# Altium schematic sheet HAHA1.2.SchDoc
size A1
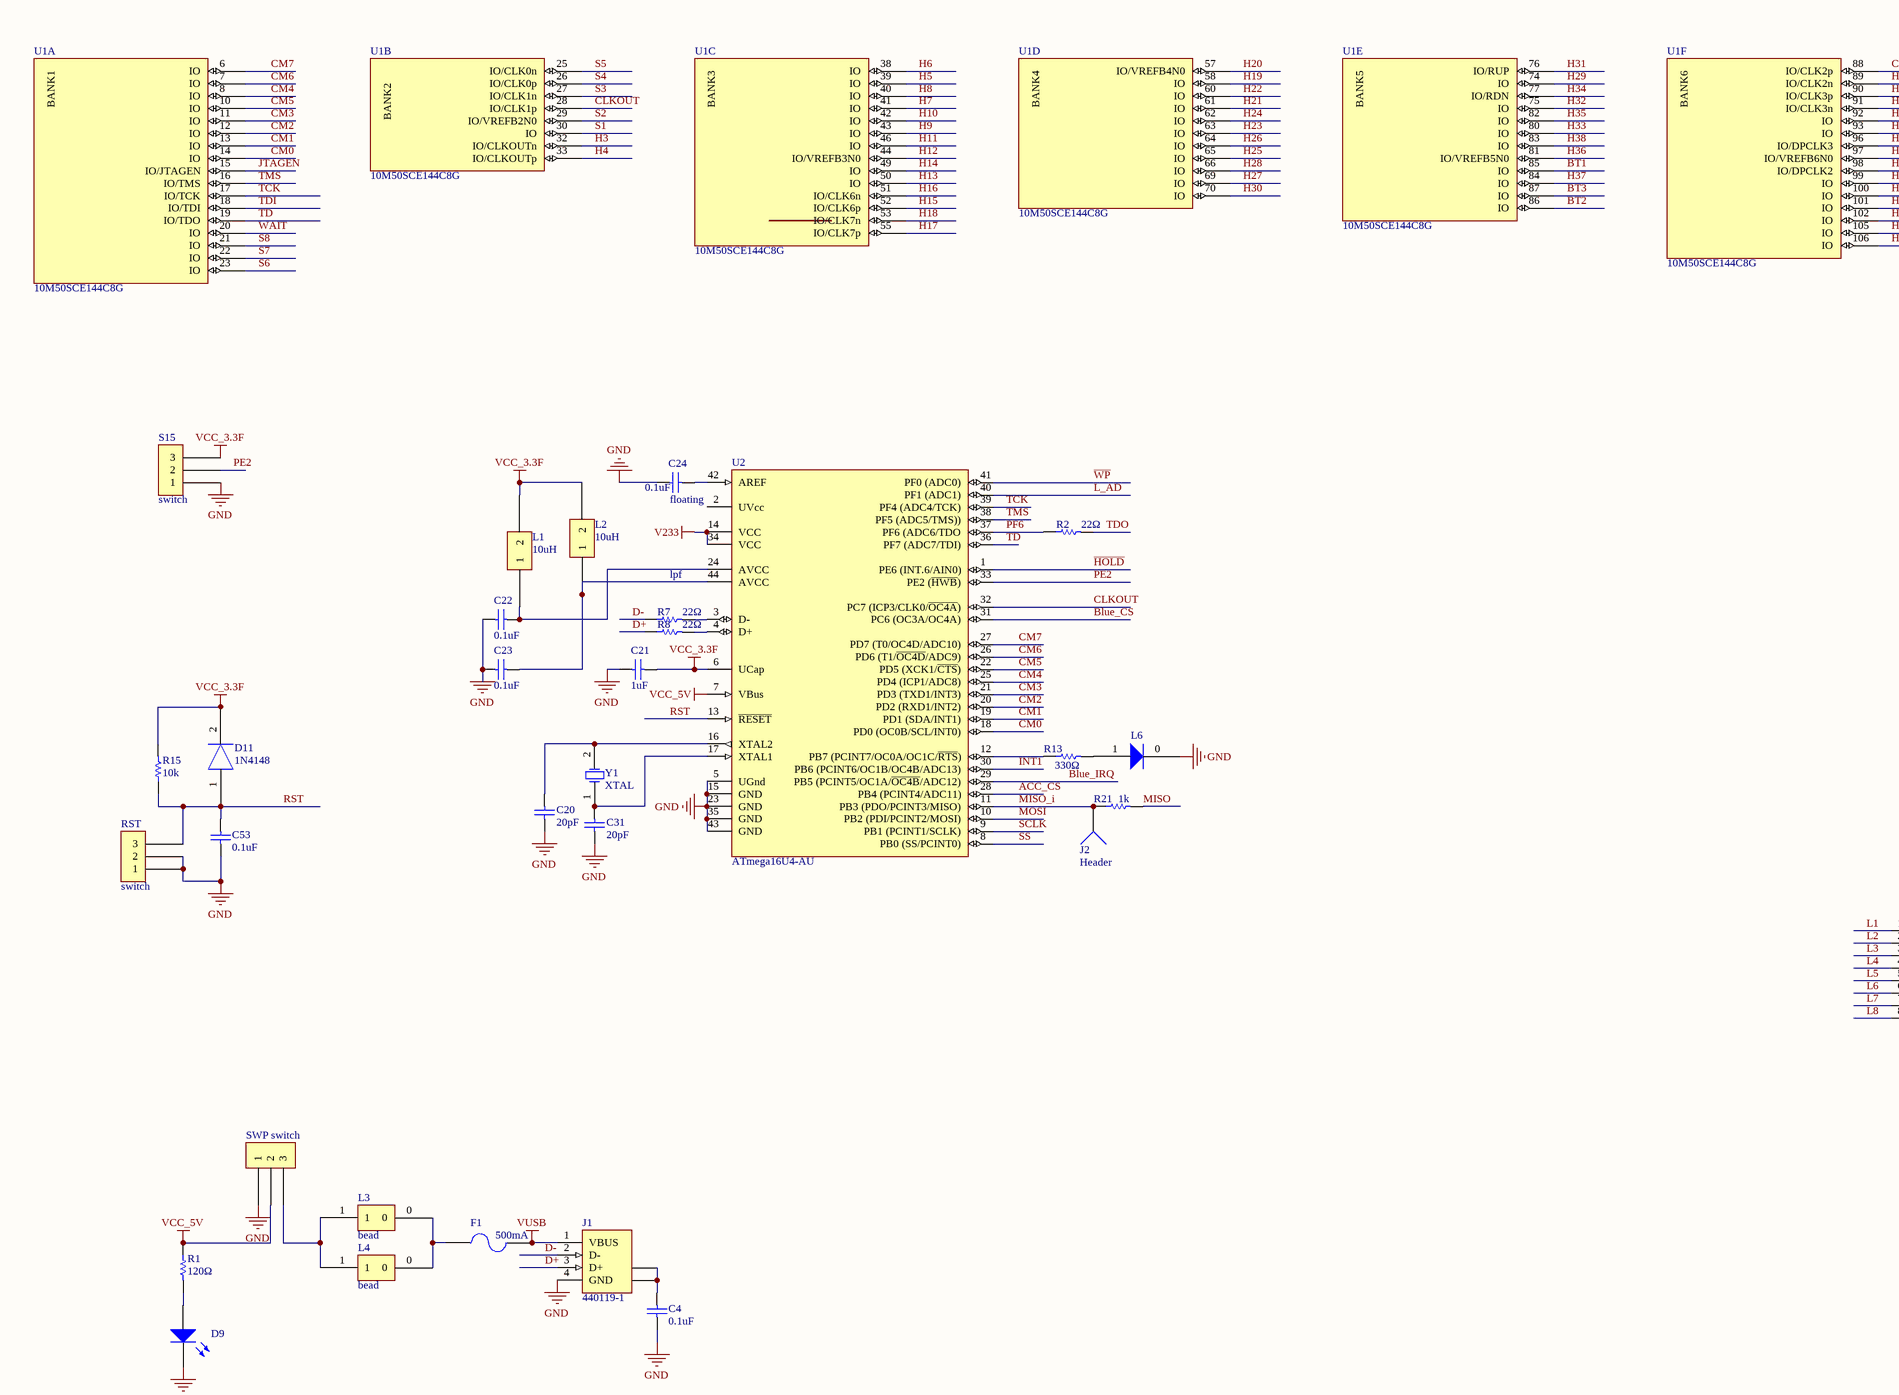
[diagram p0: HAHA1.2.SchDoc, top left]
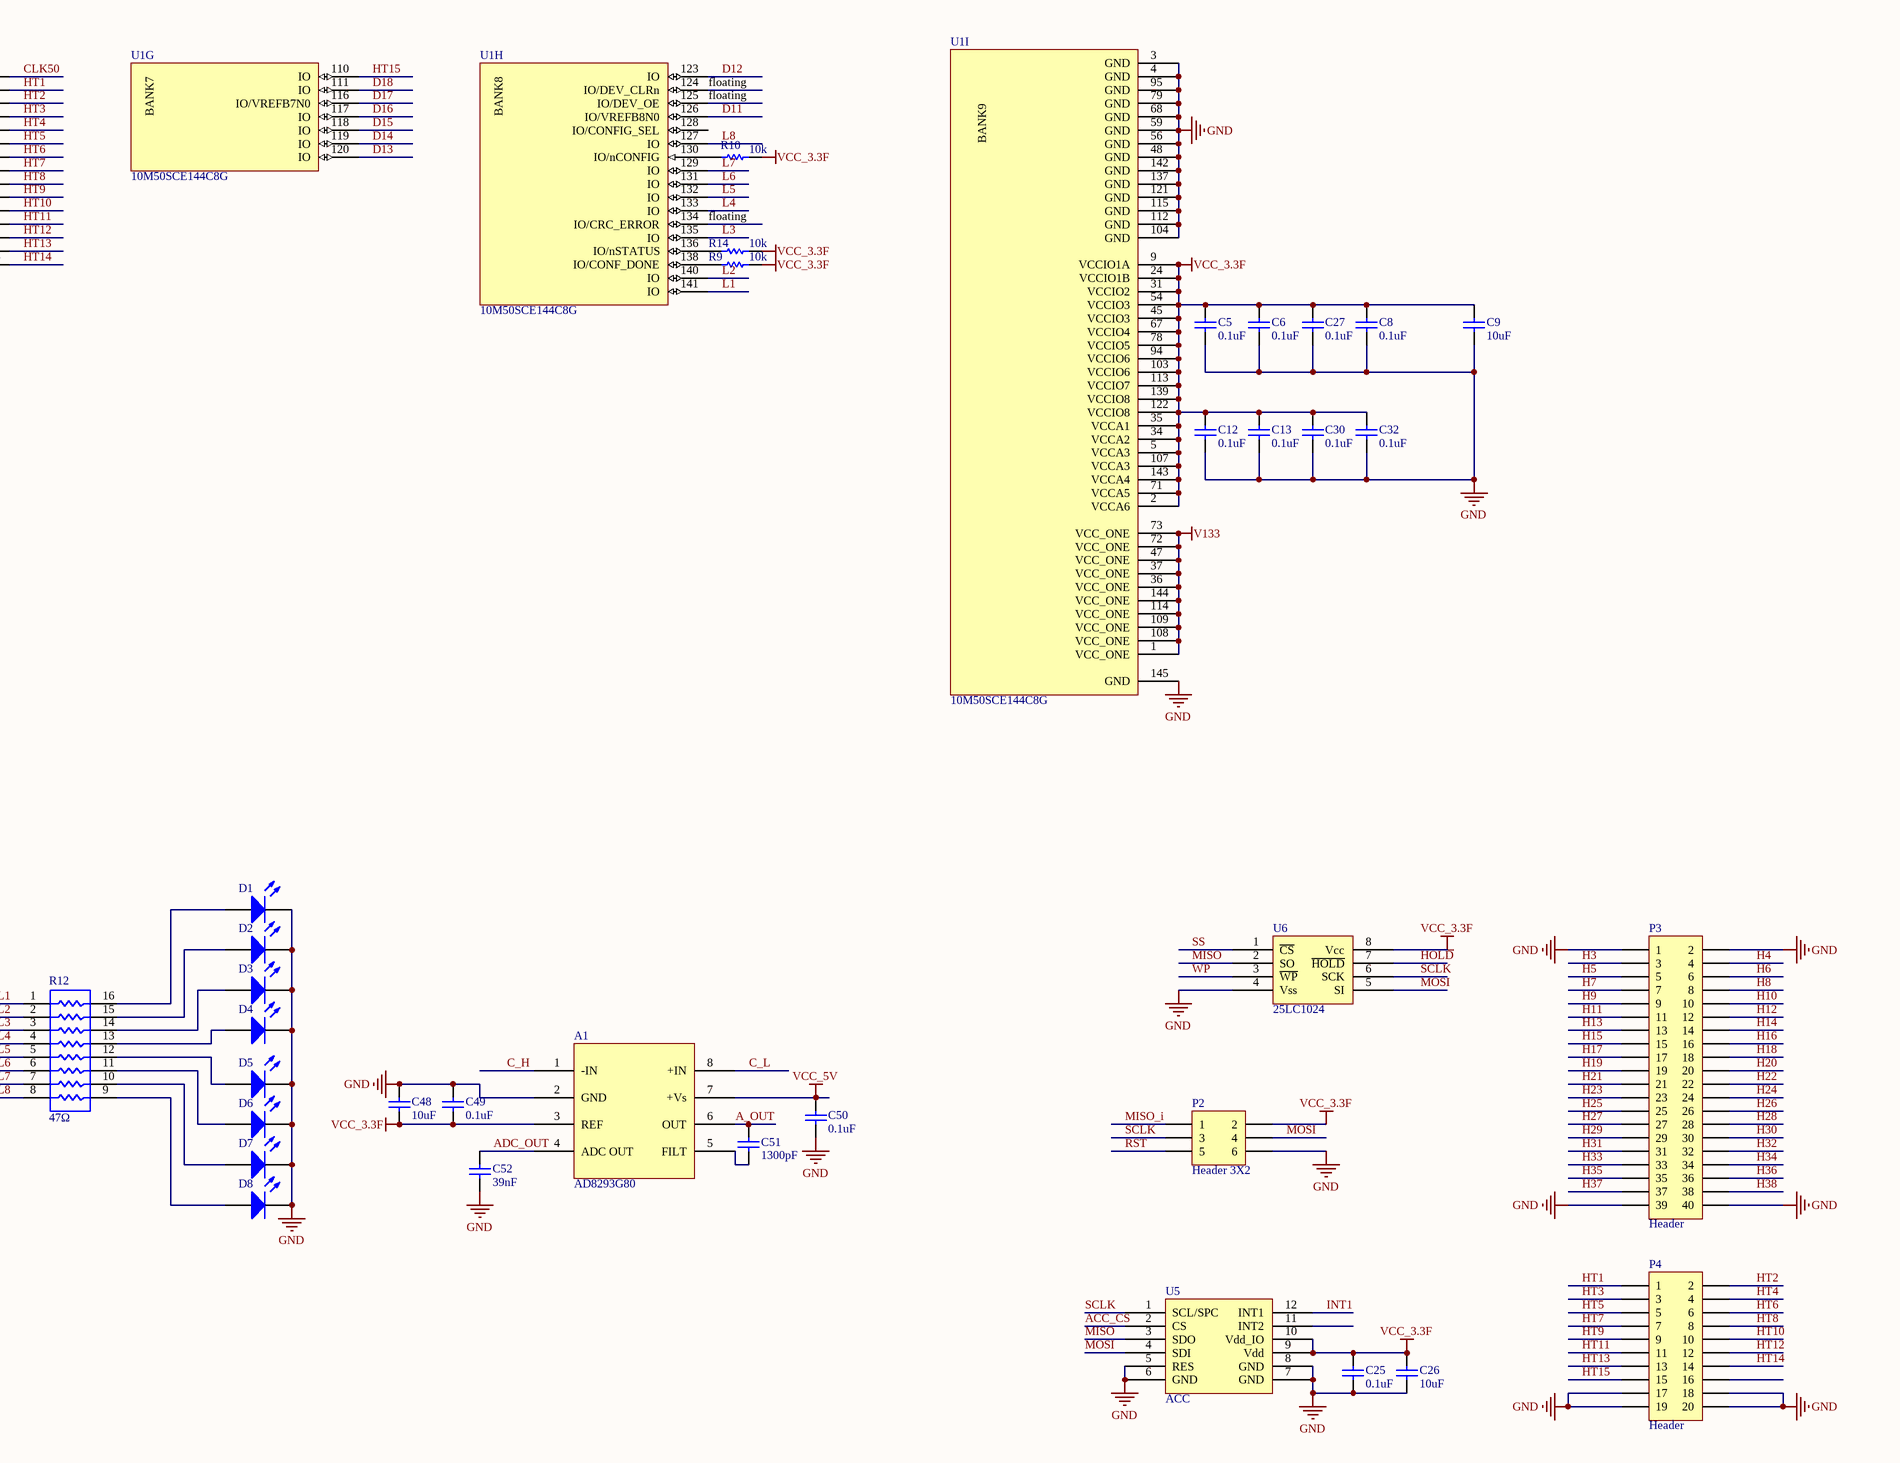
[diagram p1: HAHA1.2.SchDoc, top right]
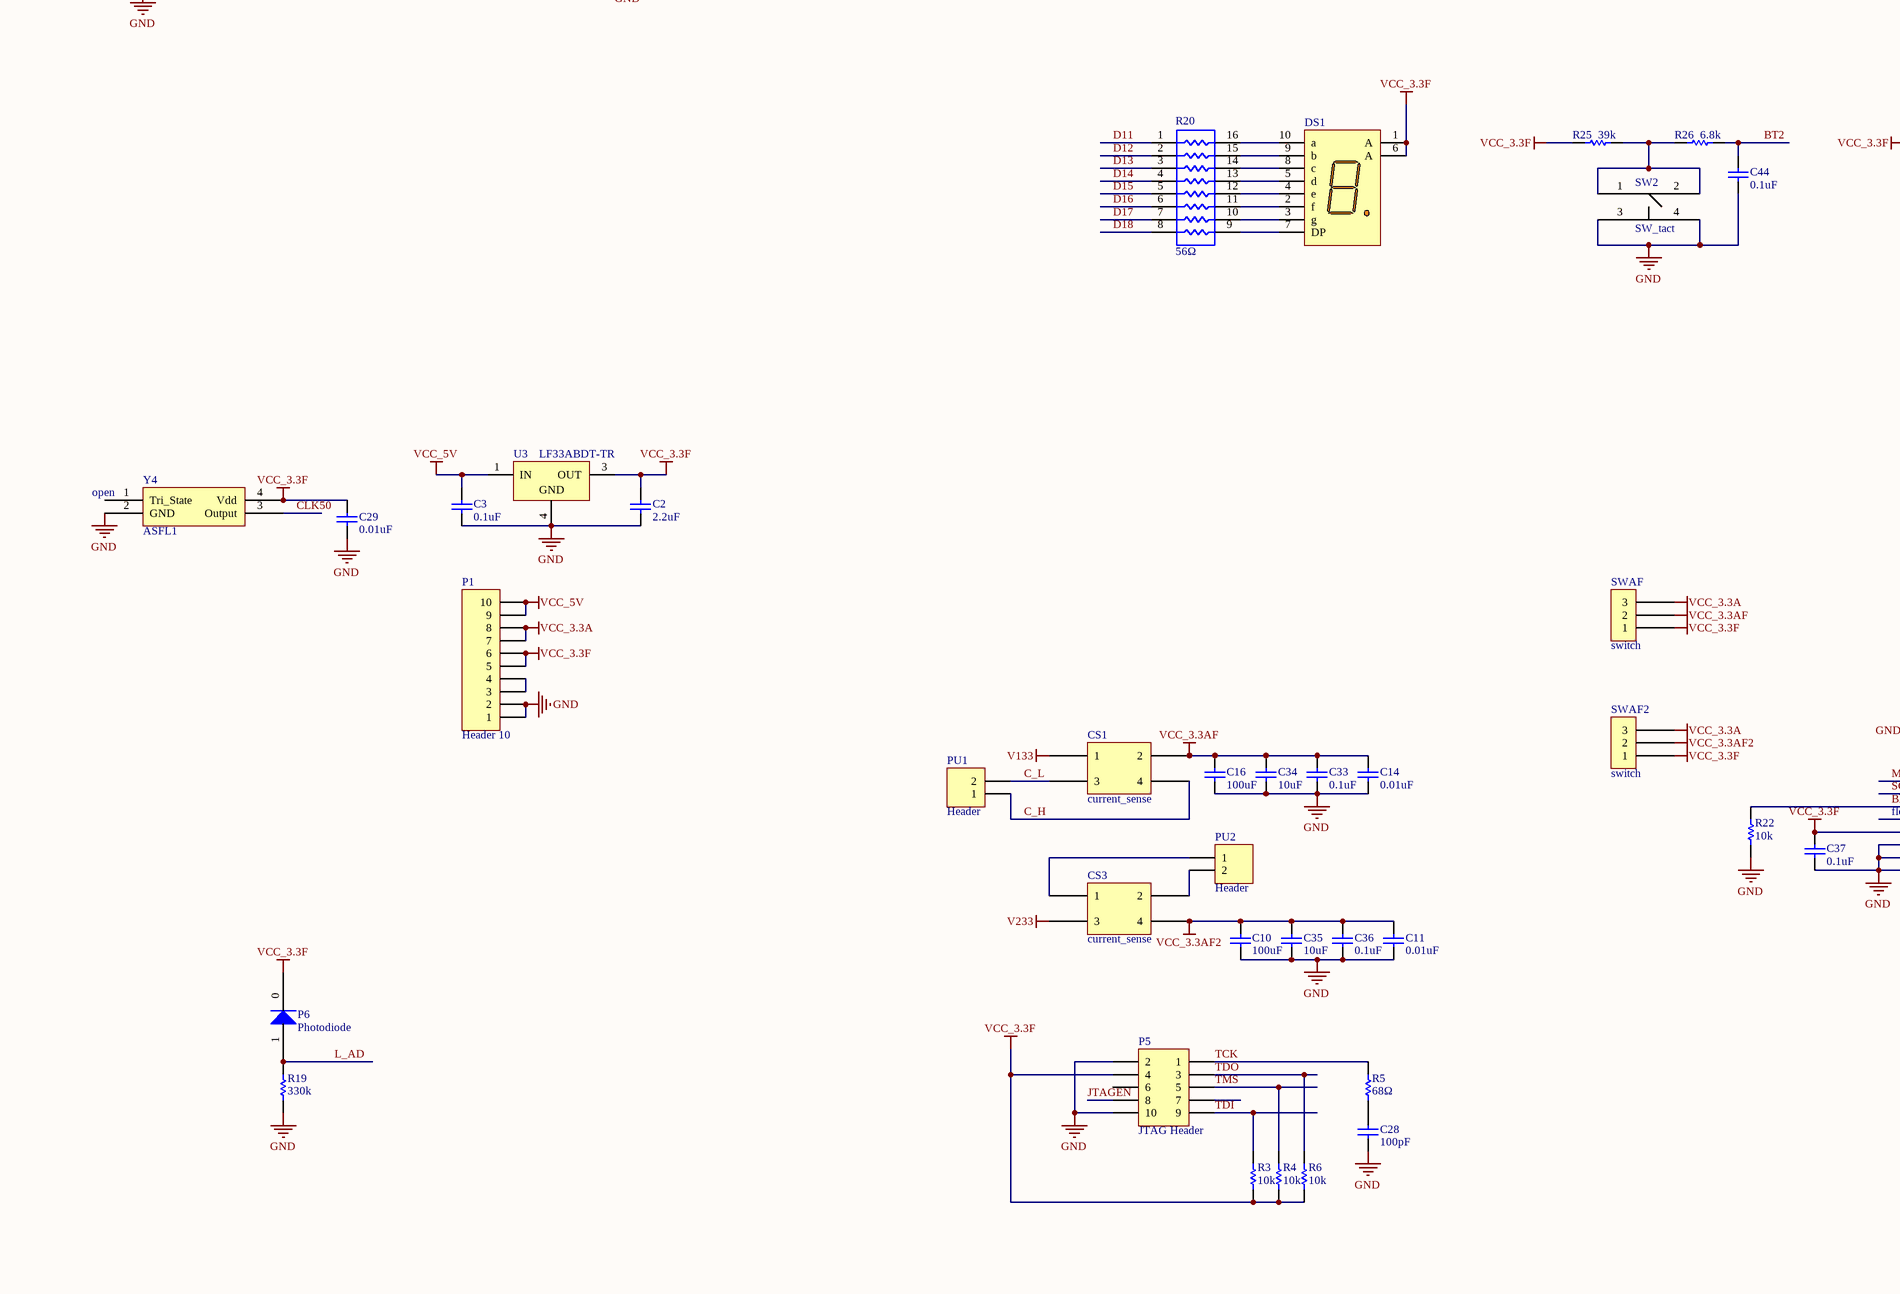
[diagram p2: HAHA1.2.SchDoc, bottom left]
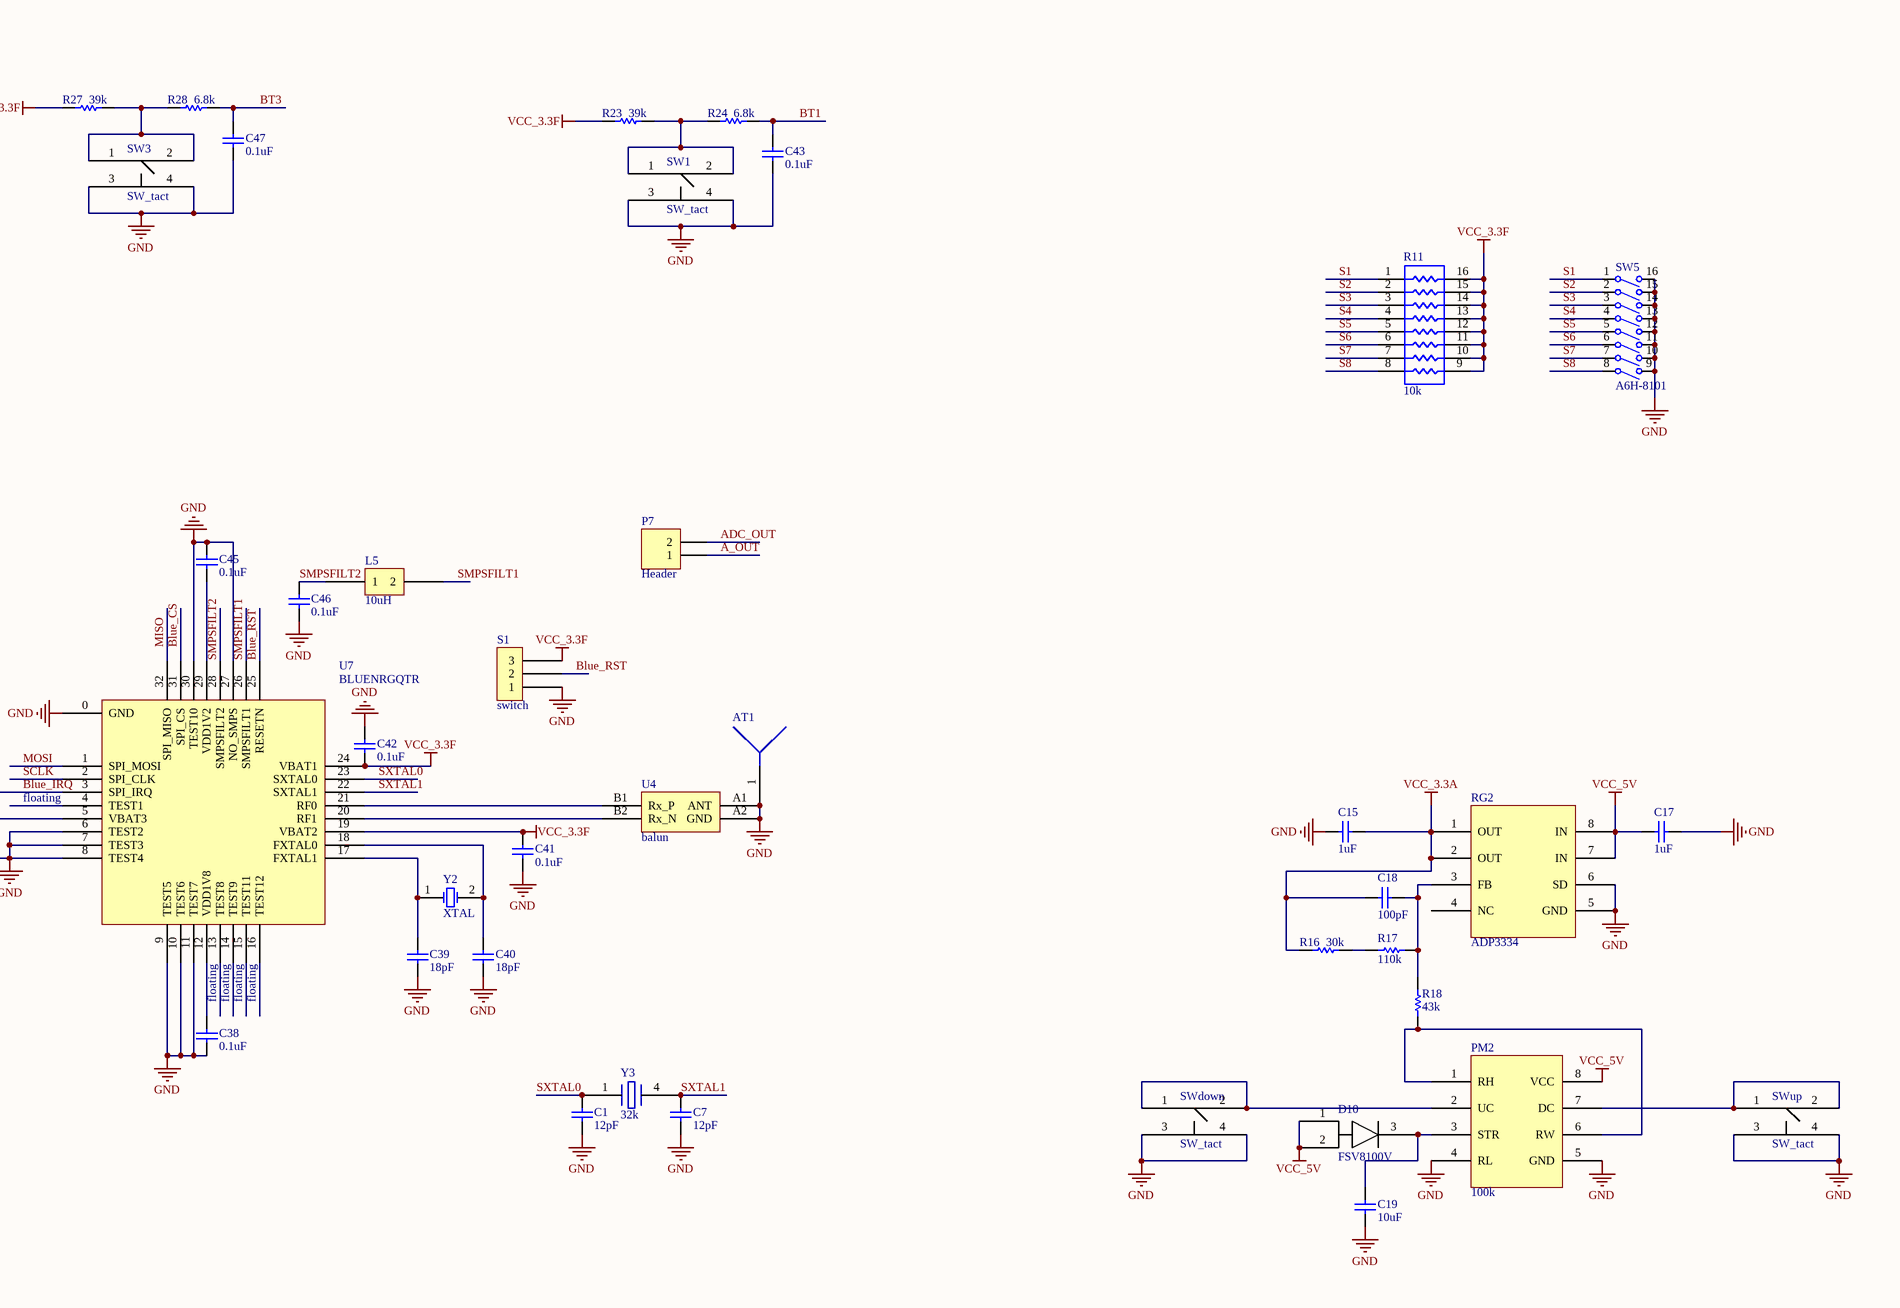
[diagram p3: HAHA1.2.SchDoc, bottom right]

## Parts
A1  AD8293G80  [SOP8_amp]
AT1  AT  [AT]  (value not drawn)
C1  12pF  [0805]
C2  2.2uF  [0805]
C3  0.1uF  [0805]
C4  0.1uF  [0805]
C5  0.1uF  [0805]
C6  0.1uF  [0805]
C7  12pF  [0805]
C8  0.1uF  [0805]
C9  10uF  [0805]
C10  100uF  [1206]
C11  0.01uF  [0805]
C12  0.1uF  [0805]
C13  0.1uF  [0805]
C14  0.01uF  [0805]
C15  1uF  [0805]
C16  100uF  [1206]
C17  1uF  [0805]
C18  100pF  [0805]
C19  10uF  [0805]
C20  20pF  [0805]
C21  1uF  [0805]
C22  0.1uF  [0805]
C23  0.1uF  [0805]
C24  0.1uF  [0805]
C25  0.1uF  [0805]
C26  10uF  [0805]
C27  0.1uF  [0805]
C28  100pF  [0805]
C29  0.01uF  [0805]
C30  0.1uF  [0805]
C31  20pF  [0805]
C32  0.1uF  [0805]
C33  0.1uF  [0805]
C34  10uF  [0805]
C35  10uF  [0805]
C36  0.1uF  [0805]
C37  0.1uF  [0805]
C38  0.1uF  [0805]
C39  18pF  [0805]
C40  18pF  [0805]
C41  0.1uF  [0805]
C42  0.1uF  [0805]
C43  0.1uF  [0805]
C44  0.1uF  [0805]
C45  0.1uF  [0805]
C46  0.1uF  [0805]
C47  0.1uF  [0805]
C48  10uF  [0805]
C49  0.1uF  [0805]
C50  0.1uF  [0805]
C51  1300pF  [0805]
C52  39nF  [0805]
C53  0.1uF  [0805]
CS1  current_sense  [Current_Sense]
CS3  current_sense  [Current_Sense]
D1  Green  [LED]  (value not drawn)
D2  Green  [LED]  (value not drawn)
D3  Green  [LED]  (value not drawn)
D4  Green  [LED]  (value not drawn)
D5  Green  [LED]  (value not drawn)
D6  Green  [LED]  (value not drawn)
D7  Green  [LED]  (value not drawn)
D8  Green  [LED]  (value not drawn)
D9  Red  [LED]  (value not drawn)
D10  FSV8100V  [FSV8100V]
D11  1N4148  [DIP2_4148]
DS1  Dpy Amber-CA  [DIP10_7seg]  (value not drawn)
F1  500mA  [fuse]
J1  440119-1  [440119]
J2  Header  [PIN1]
L1  10uH  [1210]
L2  10uH  [1210]
L3  bead  [bead]
L4  bead  [bead]
L5  10uH  [1210]
L6  make it 5mm above the board  [Led_hole]  (value not drawn)
P1  Header 10  [HDR1X10]
P2  Header 3X2  [HDR2X3]
P3  Header  [HDR2X20]
P4  Header  [HDR2X10]
P5  JTAG Header  [HDR2X5]
P6  Photodiode  [Photodiode]
P7  Header  [HDR1X2]
PM2  100k  [mSOP8]
PU1  Header  [HDR1X2]
PU2  Header  [HDR1X2]
R1  120Ω  [6-0805]
R2  22Ω  [ERA-0805]
R3  10k  [6-0805]
R4  10k  [6-0805]
R5  68Ω  [6-0805]
R6  10k  [6-0805]
R7  22Ω  [ERA-0805]
R8  22Ω  [ERA-0805]
R9  10k  [6-0805]
R10  10k  [6-0805]
R11  10k  [SOP16]
R12  47Ω  [SOP16]
R13  330Ω  [6-0805]
R14  10k  [6-0805]
R15  10k  [6-0805]
R16  30k  [6-0805]
R17  110k  [6-0805]
R18  43k  [6-0805]
R19  330k  [6-0805]
R20  56Ω  [SOP16]
R21  1k  [6-0805]
R22  10k  [6-0805]
R23  39k  [6-0805]
R24  6.8k  [6-0805]
R25  39k  [6-0805]
R26  6.8k  [6-0805]
R27  39k  [6-0805]
R28  6.8k  [6-0805]
RG2  ADP3334  [mSOP8]
RST  switch  [ck_switch]
S1  switch  [ck_switch]
S15  switch  [ck_switch]
SW1  SW_tact  [SW_tact]
SW2  SW_tact  [SW_tact]
SW3  SW_tact  [SW_tact]
SW5  A6H-8101  [DIP16_sw]
SWAF  switch  [ck_switch]
SWAF2  switch  [ck_switch]
SWdown  SW_tact  [SW_tact]
SWP  switch  [ck_switch]
SWup  SW_tact  [SW_tact]
U1  10M50SCE144C8G  [Quad144b]  (parts A,B,C,D,E,F,G,H,I of 9)
U2  ATmega16U4-AU  [44ML_N]
U3  LF33ABDT-TR  [TO-252_N]
U4  balun  [Matching_C]
U5  ACC  [ACC]
U6  25LC1024  [25LC1024]
U7  BLUENRGQTR  [Quad32]
Y1  XTAL  [SOP2]
Y2  XTAL  [CO]
Y3  32k  [SOP4]
Y4  ASFL1  [ASFL1]

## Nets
GND: A1.2(GND) AT1.1 C1.1 C2.1 C3.1 C4.1 C5.1 C6.1 C7.1 C8.1 C9.1 C10.1 C11.1 C12.1 C13.1 C14.1 C15.1 C16.1 C17.2 C19.1 C20.1 C21.1 C22.2 C23.2 C24.2 C25.1 C26.1 C27.1 C28.1 C29.1 C30.1 C31.1 C32.1 C33.1 C34.1 C35.1 C36.1 C37.1 C38.1 C39.1 C40.1 C41.1 C42.2 C43.1 C44.1 C45.2 C46.1 C47.1 C48.2 C49.2 C50.1 C52.1 C53.1 D1.2(K) D2.2(K) D3.2(K) D4.2(K) D5.2(K) D6.2(K) D7.2(K) D8.2(K) D9.2(K) J1.4(GND) L6.0 P1.1 P1.2 P2.6 P3.1 P3.2 P3.39 P3.40 P4.17 P4.18 P4.19 P4.20 P5.2 P5.10 PM2.4(RL) PM2.5(GND) R19.1 R22.1 RG2.5(GND) RG2.6(SD) RST.1 RST.2 S1.1 S15.1 SW1.3 SW1.4 SW2.3 SW2.4 SW3.3 SW3.4 SW5.9(B8) SW5.10(B7) SW5.11(B6) SW5.12(B5) SW5.13(B4) SW5.14(B3) SW5.15(B2) SW5.16(B1) SWdown.3 SWdown.4 SWP.1 SWup.3 SWup.4 U1.3(GND) U1.4(GND) U1.48(GND) U1.56(GND) U1.59(GND) U1.68(GND) U1.79(GND) U1.95(GND) U1.104(GND) U1.112(GND) U1.115(GND) U1.121(GND) U1.137(GND) U1.142(GND) U1.145(GND) U2.5(UGnd) U2.15(GND) U2.23(GND) U2.35(GND) U2.43(GND) U3.4(GND) U4.A1(ANT) U4.A2(GND) U5.5(RES) U5.6(GND) U5.7(GND) U5.8(GND) U6.4(Vss) U7.0(GND) U7.6(TEST2) U7.7(TEST3) U7.8(TEST4) U7.9(TEST5) U7.10(TEST6) U7.11(TEST7) U7.27(NO_SMPS) U7.30(TEST10) Y4.2(GND)
V133: CS1.1 U1.1(VCC_ONE) U1.36(VCC_ONE) U1.37(VCC_ONE) U1.47(VCC_ONE) U1.72(VCC_ONE) U1.73(VCC_ONE) U1.108(VCC_ONE) U1.109(VCC_ONE) U1.114(VCC_ONE) U1.144(VCC_ONE)
V233: CS3.3 U2.14(VCC) U2.34(VCC)
VCC_3.3A: C15.2 C18.1 P1.7 P1.8 R16.1 RG2.1(OUT) RG2.2(OUT) SWAF.3 SWAF2.3
VCC_3.3AF: C14.2 C16.2 C33.2 C34.2 CS1.2 SWAF.2
VCC_3.3AF2: C10.2 C11.2 C35.2 C36.2 CS3.4 SWAF2.2
VCC_3.3F: A1.3(REF) C2.2 C5.2 C6.2 C8.2 C9.2 C12.2 C13.2 C21.2 C25.2 C26.2 C27.2 C29.2 C30.2 C32.2 C37.2 C41.2 C42.1 C48.1 C49.1 D11.2 DS1.1(A) DS1.6(A) L1.2 L2.2 P1.5 P1.6 P2.2 P5.4 P6.0 R3.1 R4.1 R6.1 R9.2 R10.2 R11.9 R11.10 R11.11 R11.12 R11.13 R11.14 R11.15 R11.16 R14.2 R15.2 R23.1 R25.1 R27.1 S1.3 S15.3 SWAF.1 SWAF2.1 U1.2(VCCA6) U1.5(VCCA3) U1.9(VCCIO1A) U1.24(VCCIO1B) U1.31(VCCIO2) U1.34(VCCA2) U1.35(VCCA1) U1.45(VCCIO3) U1.54(VCCIO3) U1.67(VCCIO4) U1.71(VCCA5) U1.78(VCCIO5) U1.94(VCCIO6) U1.103(VCCIO6) U1.107(VCCA3) U1.113(VCCIO7) U1.122(VCCIO8) U1.139(VCCIO8) U1.143(VCCA4) U2.6(UCap) U3.3(OUT) U5.9(Vdd) U5.10(Vdd_IO) U6.8(Vcc) U7.5(VBAT3) U7.19(VBAT2) U7.24(VBAT1) Y4.4(Vdd)
VCC_5V: A1.7(+Vs) C3.2 C17.1 C50.2 D10.1 D10.2 P1.9 P1.10 PM2.8(VCC) R1.1 RG2.7(IN) RG2.8(IN) SWP.2 U2.7(VBus) U3.1(IN)
VUSB: F1.2 J1.1(VBUS)
A_OUT: A1.6(OUT) C51.2 P7.1
ACC_CS: U2.28(PB4_(PCINT4/ADC11)) U5.2(CS)
ADC_OUT: A1.4(ADC_OUT) C52.2 P7.2
Blue_CS: U2.31(PC6_(OC3A/OC4A)) U7.31(SPI_CS)
Blue_IRQ: R22.2 U2.29(PB5_(PCINT5/OC1A/~{OC4B}/ADC12)) U7.3(SPI_IRQ)
Blue_RST: S1.2 U7.25(RESETN)
BT1: C43.2 R24.2 U1.85(IO)
BT2: C44.2 R26.2 U1.86(IO)
BT3: C47.2 R28.2 U1.87(IO)
C_H: A1.1(-IN) CS1.4 PU1.1
C_L: A1.8(+IN) CS1.3 PU1.2
CLK50: U1.88(IO/CLK2p) Y4.3(Output)
CLKOUT: U1.28(IO/CLK1p) U2.32(PC7_(ICP3/CLK0/~{OC4A}))
CM0: U1.14(IO) U2.18(PD0_(OC0B/SCL/INT0))
CM1: U1.13(IO) U2.19(PD1_(SDA/INT1))
CM2: U1.12(IO) U2.20(PD2_(RXD1/INT2))
CM3: U1.11(IO) U2.21(PD3_(TXD1/INT3))
CM4: U1.8(IO) U2.25(PD4_(ICP1/ADC8))
CM5: U1.10(IO) U2.22(PD5_(XCK1/~{CTS}))
CM6: U1.7(IO) U2.26(PD6_(T1/~{OC4D}/ADC9))
CM7: U1.6(IO) U2.27(PD7_(T0/OC4D/ADC10))
D11: R20.1 U1.126(IO/VREFB8N0)
D12: R20.2 U1.123(IO)
D13: R20.3 U1.120(IO)
D14: R20.4 U1.119(IO)
D15: R20.5 U1.118(IO)
D16: R20.6 U1.117(IO)
D17: R20.7 U1.116(IO/VREFB7N0)
D18: R20.8 U1.111(IO)
D+: J1.3(D+) R8.1
D-: J1.2(D-) R7.1
H3: P3.3 U1.32(IO/CLKOUTn)
H4: P3.4 U1.33(IO/CLKOUTp)
H5: P3.5 U1.39(IO)
H6: P3.6 U1.38(IO)
H7: P3.7 U1.41(IO)
H8: P3.8 U1.40(IO)
H9: P3.9 U1.43(IO)
H10: P3.10 U1.42(IO)
H11: P3.11 U1.46(IO)
H12: P3.12 U1.44(IO/VREFB3N0)
H13: P3.13 U1.50(IO)
H14: P3.14 U1.49(IO)
H15: P3.15 U1.52(IO/CLK6p)
H16: P3.16 U1.51(IO/CLK6n)
H17: P3.17 U1.55(IO/CLK7p)
H18: P3.18 U1.53(IO/CLK7n)
H19: P3.19 U1.58(IO)
H20: P3.20 U1.57(IO/VREFB4N0)
H21: P3.21 U1.61(IO)
H22: P3.22 U1.60(IO)
H23: P3.23 U1.63(IO)
H24: P3.24 U1.62(IO)
H25: P3.25 U1.65(IO)
H26: P3.26 U1.64(IO)
H27: P3.27 U1.69(IO)
H28: P3.28 U1.66(IO)
H29: P3.29 U1.74(IO)
H30: P3.30 U1.70(IO)
H31: P3.31 U1.76(IO/RUP)
H32: P3.32 U1.75(IO)
H33: P3.33 U1.80(IO)
H34: P3.34 U1.77(IO/RDN)
H35: P3.35 U1.82(IO)
H36: P3.36 U1.81(IO/VREFB5N0)
H37: P3.37 U1.84(IO)
H38: P3.38 U1.83(IO)
~{HOLD}: U2.1(PE6_(INT.6/AIN0)) U6.7(~{HOLD})
HT1: P4.1 U1.89(IO/CLK2n)
HT2: P4.2 U1.90(IO/CLK3p)
HT3: P4.3 U1.91(IO/CLK3n)
HT4: P4.4 U1.92(IO)
HT5: P4.5 U1.93(IO)
HT6: P4.6 U1.96(IO/DPCLK3)
HT7: P4.7 U1.97(IO/VREFB6N0)
HT8: P4.8 U1.98(IO/DPCLK2)
HT9: P4.9 U1.99(IO)
HT10: P4.10 U1.100(IO)
HT11: P4.11 U1.101(IO)
HT12: P4.12 U1.102(IO)
HT13: P4.13 U1.105(IO)
HT14: P4.14 U1.106(IO)
HT15: P4.15 U1.110(IO)
INT1: U2.30(PB6_(PCINT6/OC1B/OC4B/ADC13)) U5.12(INT1)
JTAGEN: P5.8 U1.15(IO/JTAGEN)
L1: R12.1 U1.141(IO)
L2: R12.2 U1.140(IO)
L3: R12.3 U1.135(IO)
L4: R12.4 U1.133(IO)
L5: R12.5 U1.132(IO)
L6: R12.6 U1.131(IO)
L7: R12.7 U1.129(IO)
L8: R12.8 U1.127(IO)
L_AD: P6.1 R19.2 U2.40(PF1_(ADC1))
MISO: R21.2 U5.3(SDO) U6.2(SO) U7.32(SPI_MISO)
MISO_i: J2.1 P2.1 R21.1 U2.11(PB3_(PDO/PCINT3/MISO))
MOSI: P2.4 U2.10(PB2_(PDI/PCINT2/MOSI)) U5.4(SDI) U6.5(SI) U7.1(SPI_MOSI)
PE2: S15.2 U2.33(PE2_(~{HWB}))
PF6: R2.1 U2.37(PF6_(ADC6/TDO)
RST: C53.2 D11.1 P2.5 R15.1 RST.3 U2.13(~{RESET})
S1: R11.1 SW5.1(A1) U1.30(IO)
S2: R11.2 SW5.2(A2) U1.29(IO/VREFB2N0)
S3: R11.3 SW5.3(A3) U1.27(IO/CLK1n)
S4: R11.4 SW5.4(A4) U1.26(IO/CLK0p)
S5: R11.5 SW5.5(A5) U1.25(IO/CLK0n)
S6: R11.6 SW5.6(A6) U1.23(IO)
S7: R11.7 SW5.7(A7) U1.22(IO)
S8: R11.8 SW5.8(A8) U1.21(IO)
SCLK: P2.3 U2.9(PB1_(PCINT1/SCLK)) U5.1(SCL/SPC) U6.6(SCK) U7.2(SPI_CLK)
SMPSFILT1: L5.2 U7.26(SMPSFILT1)
SMPSFILT2: C46.2 L5.1 U7.28(SMPSFILT2)
SS: U2.8(PB0_(SS/PCINT0)) U6.1(~{CS})
SXTAL0: C1.2 U7.23(SXTAL0) Y3.1
SXTAL1: C7.2 U7.22(SXTAL1) Y3.4
TCK: P5.1 R5.2 U1.17(IO/TCK) U2.39(PF4_(ADC4/TCK))
TD: U1.19(IO/TDO) U2.36(PF7_(ADC7/TDI))
TDI: P5.9 R3.2 U1.18(IO/TDI)
TDO: P5.3 R2.2 R6.2
TMS: P5.5 R4.2 U1.16(IO/TMS) U2.38(PF5_(ADC5/TMS)))
~{WP}: U2.41(PF0_(ADC0)) U6.3(~{WP})
WAIT: U1.20(IO)
NetA1_5: A1.5(FILT) C51.1
NetC4_2: C4.2 J1.5(SHLD) J1.6(SHLD)
NetC18_2: C18.2 R17.2 R18.2 RG2.3(FB)
NetC19_2: C19.2 D10.3 PM2.3(STR)
NetC20_2: C20.2 U2.16(XTAL2) Y1.2(OSC2)
NetC22_1: C22.1 L1.1 U2.24(AVCC)
NetC23_1: C23.1 L2.1 U2.44(AVCC)
NetC24_1: C24.1 U2.42(AREF)
NetC28_2: C28.2 R5.1
NetC31_2: C31.2 U2.17(XTAL1) Y1.1(OSC1)
NetC38_2: C38.2 U7.12(VDD1V8)
NetC39_2: C39.2 U7.17(FXTAL1) Y2.1(OSC1)
NetC40_2: C40.2 U7.18(FXTAL0) Y2.2(OSC2)
NetC45_1: C45.1 U7.29(VDD1V2)
NetCS3_1: CS3.1 PU2.1
NetCS3_2: CS3.2 PU2.2
NetD1_1: D1.1(A) R12.16
NetD2_1: D2.1(A) R12.15
NetD3_1: D3.1(A) R12.14
NetD4_1: D4.1(A) R12.13
NetD5_1: D5.1(A) R12.12
NetD6_1: D6.1(A) R12.11
NetD7_1: D7.1(A) R12.10
NetD8_1: D8.1(A) R12.9
NetD9_1: D9.1(A) R1.2
NetDS1_2: DS1.2(f) R20.11
NetDS1_3: DS1.3(g) R20.10
NetDS1_4: DS1.4(e) R20.12
NetDS1_5: DS1.5(d) R20.13
NetDS1_7: DS1.7(DP) R20.9
NetDS1_8: DS1.8(c) R20.14
NetDS1_9: DS1.9(b) R20.15
NetDS1_10: DS1.10(a) R20.16
NetF1_1: F1.1 L3.0 L4.0
NetL3_1: L3.1 L4.1 SWP.3
NetL6_1: L6.1 R13.2
NetP1_3: P1.3 P1.4
NetPM2_1: PM2.1(RH) PM2.6(RW) R18.1
NetPM2_2: PM2.2(UC) SWdown.1 SWdown.2
NetPM2_7: PM2.7(DC) SWup.1 SWup.2
NetR7_2: R7.2 U2.3(D-)
NetR8_2: R8.2 U2.4(D+)
NetR9_1: R9.1 U1.138(IO/CONF_DONE)
NetR10_1: R10.1 U1.130(IO/nCONFIG)
NetR13_1: R13.1 U2.12(PB7_(PCINT7/OC0A/OC1C/~{RTS}))
NetR14_1: R14.1 U1.136(IO/nSTATUS)
NetR16_2: R16.2 R17.1
NetR23_2: R23.2 R24.1 SW1.1 SW1.2
NetR25_2: R25.2 R26.1 SW2.1 SW2.2
NetR27_2: R27.2 R28.1 SW3.1 SW3.2
NetU4_B1: U4.B1(Rx_P) U7.21(RF0)
NetU4_B2: U4.B2(Rx_N) U7.20(RF1)

Not connected (* = marked no-connect by the designer): P4 16; P5 6 7; RG2 4(NC); U1 124(IO/DEV_CLRn) 125(IO/DEV_OE) 128(IO/CONFIG_SEL) 134(IO/CRC_ERROR); U2 2(UVcc); U5 11(INT2); U7 4(TEST1) 13(TEST8) 14(TEST9) 15(TEST11) 16(TEST12); Y4 1(Tri_State)

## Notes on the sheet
- (near U1) floating
- floating
- lpf
- (near Y4) open
- (near U7) floating

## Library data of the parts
A1 = AD8293G80: Manufacturer: Analog devices; Manufacturer No: AD8293G80ARJZ-R7
AT1 = AT: Manufacturer: (this is not a component)
C1 C7 = C0805: Ceramic Chip Capacitor - Standard; Manufacturer: Kemet; Manufacturer No: C0805C120J5GACTU; Note: Footprint corresponds to dimensions for bulk cassette packaging. This case size has tightened tolerances.
C2 = C0805: Ceramic Chip Capacitor - Standard; Manufacturer: Kemet; Manufacturer No: C0805C225K8RACTU; Note: Footprint corresponds to dimensions for bulk cassette packaging. This case size has tightened tolerances.
C3-C6 C8 C12 C13 C22-C25 C27 C30 C32 C33 C36-C38 C41-C47 C49 C50 C53 = C0805: Ceramic Chip Capacitor - Standard; Manufacturer: Kemet; Manufacturer No: C0805C104J5RACTU; Note: Footprint corresponds to dimensions for bulk cassette packaging. This case size has tightened tolerances.
C9 C19 C26 C34 C35 C48 = C0805: Ceramic Chip Capacitor - Standard; Manufacturer: Kemet; Manufacturer No: C0805C106K8PACTU; Note: Footprint corresponds to dimensions for bulk cassette packaging. This case size has tightened tolerances.
C10 C16 = C1206: Ceramic Chip Capacitor - Standard; Manufacturer: Kemet; Manufacturer No: C1206C107M9PACTU
C11 C14 C29 = C0805: Ceramic Chip Capacitor - Standard; Manufacturer: Kemet; Manufacturer No: C0805C103K5RACTU; Note: Footprint corresponds to dimensions for bulk cassette packaging. This case size has tightened tolerances.
C15 C17 C21 = C0805: Ceramic Chip Capacitor - Standard; Manufacturer: Kemet; Manufacturer No: C0805C105K4RACTU; Note: Footprint corresponds to dimensions for bulk cassette packaging. This case size has tightened tolerances.
C18 C28 = C0805: Ceramic Chip Capacitor - Standard; Manufacturer No: C0805C101J3GACTU; Manufacturer: Kemet; Note: Footprint corresponds to dimensions for bulk cassette packaging. This case size has tightened tolerances.
C20 C31 = C0805: Ceramic Chip Capacitor - Standard; Manufacturer: Kemet; Manufacturer No: C0805C200J1GACTU; Note: Footprint corresponds to dimensions for bulk cassette packaging. This case size has tightened tolerances.
C39 C40 = C0805: Ceramic Chip Capacitor - Standard; Manufacturer: Kemet; Manufacturer No: C0805C180J5GACTU; Note: Footprint corresponds to dimensions for bulk cassette packaging. This case size has tightened tolerances.
C51 = C0805: Ceramic Chip Capacitor - Standard; Manufacturer: Kemet; Manufacturer No: C0805C132J5GACTU; Note: Footprint corresponds to dimensions for bulk cassette packaging. This case size has tightened tolerances.
C52 = C0805: Ceramic Chip Capacitor - Standard; Manufacturer: Kemet; Manufacturer No: C0805C393K5RACTU; Note: Footprint corresponds to dimensions for bulk cassette packaging. This case size has tightened tolerances.
CS1 CS3 = current_sense: Manufacturer: LVK Series; Manufacturer No: LVK12R010DER
D1-D8 = LED3: Typical BLUE SiC LED; Manufacturer: Lite on; Manufacturer No: LTST-C190KGKT
D9 = LED3: Typical BLUE SiC LED; Manufacturer: Lite on; Manufacturer No: LTST-C190KRKT
D10 = FSV8100V: Manufacturer: Fairchild Semiconductor
D11 = 1N4148: Manufacturer: Fairchild Semiconductor
DS1 = Dpy Amber-CA: 7.62 mm Black Surface Orange 7-Segment Display: CA, RH DP; Manufacturer: Lite on; MinimumIntensity: 354 ucd; Note: IF = 5 mA; Note: Pins 1 and 6 are redundant Anodes.
F1 = Fuse 2: Fuse; Manufacturer: Bel Fuse; Manufacturer No: 0697H1000-02
J1 = 440119-1: USB 1.1, Right Angle, Thru-Hole, B Type, Receptacle, 4 Position, Beige; Manufacturer: Assmann WSW Components; Manufacturer No: AU-Y1007; ContactMaterial: Copper Alloy; ContactPlating: Gold Flash over Nickel; TerminationLength: 2.84mm [0.112in.]; PCB_Layout: Complies with manufacturer's recommendation.; DrillSize: Corresponds to nominal value.; PanelGround: Without
J2 = Socket: Manufacturer No: 961210-6404-AR; Manufacturer: 3M
L1 L2 L5 = inductor: Manufacturer: EPCOS / TDK; Manufacturer No: B82422T1103K
L3 L4 = bead: Manufacturer: TDK Corporation; Manufacturer No: MPZ1608S101ATAH0
L6 = Led_hole: Manufacturer: Lite on; Manufacturer No: LTL2R3KRD-EM
P1 = Header 10: Header, 10-Pin; Manufacturer: 3M; Manufacturer No: 929870-01-02-RA
P2 = Header 3X2: Header, 3-Pin, Dual row; Manufacturer: 3M; Manufacturer No: 961210-6404-AR
P3 = Header 20X2: Manufacturer: 3M; Manufacturer No: 961210-6404-AR
P4 = Header 10X2: Manufacturer: 3M; Manufacturer No: 961210-6404-AR
P5 = Header 5X2: Header, 5-Pin, Dual row; Manufacturer: 3M; Manufacturer No: 961210-6404-AR
P6 = Photodiode: Manufacturer: Optek / TT Electronics; Manufacturer No: OP980
P7 PU1 PU2 = Header 2: Manufacturer No: 961210-6404-AR; Manufacturer: 3M
PM2 = DS1809: Manufacturer: Maxim Integrated; Manufacturer No: DS1809U-100+
R1 = ERJ6EN: Precision Thick Film Chip Resistor, 10 Ohm to 2.2M Ohm Range, 1% Tolerance, 0805 Size, 0.1 W; Manufacturer: Panasonic; Manufacturer No: ERJ-6ENF1200V
R2 R7 R8 = ERA6Y: Rectangular Thick Film Chip Resistor, 10 Ohm to 1M Ohm Range, 0.1% and 0.5% Tolerance, 0805 Size, 0.1 W; Manufacturer: Panasonic; Manufacturer No: ERJ-6GEYJ220V; Note: If flow soldering, adjust pad width of PCB Footprint to 0.7 - 0.8 times the width of the resistor.
R3 R4 R6 R9 R10 R14 R15 R22 = ERJ6GE: Thick Film Chip Resistor, 1 Ohm to 10M Ohm Range, 5% Tolerance, 0805 Size, 0.125 W; Manufacturer: Panasonic; Manufacturer No: ERJ-6GEYJ103V; Note: If flow soldering, adjust pad width of PCB Footprint to 0.7 - 0.8 times the width of the resistor.
R5 = ERJ6EN: Precision Thick Film Chip Resistor, 10 Ohm to 2.2M Ohm Range, 1% Tolerance, 0805 Size, 0.1 W; Manufacturer: Panasonic; Manufacturer No: ERJ-6ENF68R0V
R11 = Res Pack3: Isolated Resistor Network; Manufacturer: Bourns; Manufacturer No: 4816P-1-103LF
R12 = Res Pack3: Isolated Resistor Network; Manufacturer: Bourns; Manufacturer No: 4816P-1-470LF
R13 = ERJ6EN: Precision Thick Film Chip Resistor, 10 Ohm to 2.2M Ohm Range, 1% Tolerance, 0805 Size, 0.1 W; Manufacturer: Panasonic; Manufacturer No: ERJ-6ENF3300V
R16 = ERJ6GE: Thick Film Chip Resistor, 1 Ohm to 10M Ohm Range, 5% Tolerance, 0805 Size, 0.125 W; Manufacturer: Panasonic; Manufacturer No: ERJ-6GEYJ303V; Note: If flow soldering, adjust pad width of PCB Footprint to 0.7 - 0.8 times the width of the resistor.
R17 = ERJ6GE: Thick Film Chip Resistor, 1 Ohm to 10M Ohm Range, 5% Tolerance, 0805 Size, 0.125 W; Manufacturer: Panasonic; Manufacturer No: ERJ-6ENF1103V; Note: If flow soldering, adjust pad width of PCB Footprint to 0.7 - 0.8 times the width of the resistor.
R18 = ERJ6EN: Precision Thick Film Chip Resistor, 10 Ohm to 2.2M Ohm Range, 1% Tolerance, 0805 Size, 0.1 W; Manufacturer: Panasonic; Manufacturer No: ERJ-6GEYJ433V
R19 = ERJ6EN: Precision Thick Film Chip Resistor, 10 Ohm to 2.2M Ohm Range, 1% Tolerance, 0805 Size, 0.1 W; Manufacturer: Panasonic; Manufacturer No: ERJ-6ENF3303V
R20 = Res Pack3: Isolated Resistor Network; Manufacturer: Bourns; Manufacturer No: 4816P-1-560LF
R21 = ERJ6GE: Thick Film Chip Resistor, 1 Ohm to 10M Ohm Range, 5% Tolerance, 0805 Size, 0.125 W; Manufacturer: Panasonic; Manufacturer No: ERJ-6GEYJ102V; Note: If flow soldering, adjust pad width of PCB Footprint to 0.7 - 0.8 times the width of the resistor.
R23 R25 R27 = ERJ6GE: Thick Film Chip Resistor, 1 Ohm to 10M Ohm Range, 5% Tolerance, 0805 Size, 0.125 W; Manufacturer: Panasonic; Manufacturer No: ERJ-6GEYJ393V; Note: If flow soldering, adjust pad width of PCB Footprint to 0.7 - 0.8 times the width of the resistor.
R24 R26 R28 = ERJ6GE: Thick Film Chip Resistor, 1 Ohm to 10M Ohm Range, 5% Tolerance, 0805 Size, 0.125 W; Manufacturer: Panasonic; Manufacturer No: ERJ-6GEYJ682V; Note: If flow soldering, adjust pad width of PCB Footprint to 0.7 - 0.8 times the width of the resistor.
RG2 = ADP3334: Manufacturer: Analog Devices; PN: ADP3334ARMZ-REEL7
RST S1 S15 SWAF SWAF2 SWP = ck_switch: Manufacturer: C&K Components; Manufacturer No: OS102011MS2QN1
SW1-SW3 SWdown SWup = SW_tact: Manufacturer: C&K Components; Manufacturer No: PTS645SM43SMTR92 LFS
SW5 = A6H-8101: Ultra-Low Profile, Half-Pitch, SM, Slide DIP Switch, Flat Actuator, White Striker, 8 Position, SPST, Std. Model; Manufacturer: CTS Electronic Components; Manufacturer No: 206-8ST; PCB_Layout: Complies with manufacturer's recommendation.
U1 = 10M50SCE144C8G: Manufacturer: Altera
U2 = ATmega16U4-AU: 8-bit AVR Microcontroller, 2.7-5.5V, 16KB Flash, 1.25KB EEPROM, 512 Bytes SRAM, USB Controller, 44-pin TQFP, Industrial Grade (-40°C to 85°C); Manufacturer: Atmel
U3 = LF33ABDT-TR: 500mA, Very Low Drop (0.45V) Voltage Regulator, 3.3V, 3-Pin DPAK, Tape and Reel; Manufacturer: STMicroelectronics
U4 = balun: Manufacturer No: BALF-NRG-01D3; Manufacturer: STMicroelectronics
U5 = ACC: Manufacturer: STMicroelectronics; Manufacturer No: LIS2DE12TR
U6 = 25LC1024: Manufacturer: Microchip; Manufacturer No: 25LC1024-E/SM
U7 = BLUENRGQTR: Manufacturer: STMicroelectronics
Y1 = XTAL: Crystal Oscillator; Manufacturer No: FOXSDLF/080-20; Manufacturer: Fox
Y2 = XTAL: Crystal Oscillator; Manufacturer No: ABLS-16.000MHZ-B4-T; Manufacturer: Abracon
Y3 = 32k: Manufacturer: Abracon; Manufacturer No: ABS25-32.000KHZ-T
Y4 = ASFL1: Manufacturer: Abracon LLC; Manufacturer No: ASFL1-50.000MHZ-EC-T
